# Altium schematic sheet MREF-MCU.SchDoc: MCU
size A4; CompanyName: TRINAMIC; DocumentNumber: 2; SheetNumber: 2; SheetTotal: 5; Author: Indrek Rebane; DrawnBy: Indrek Rebane; Engineer: Indrek Rebane; Organization: Hedgehog OÜ; Address1: Waterloohain 5; Address2: 22769 Hamburg; Address3: Germany; Address4: tmc_info@trinamic.com
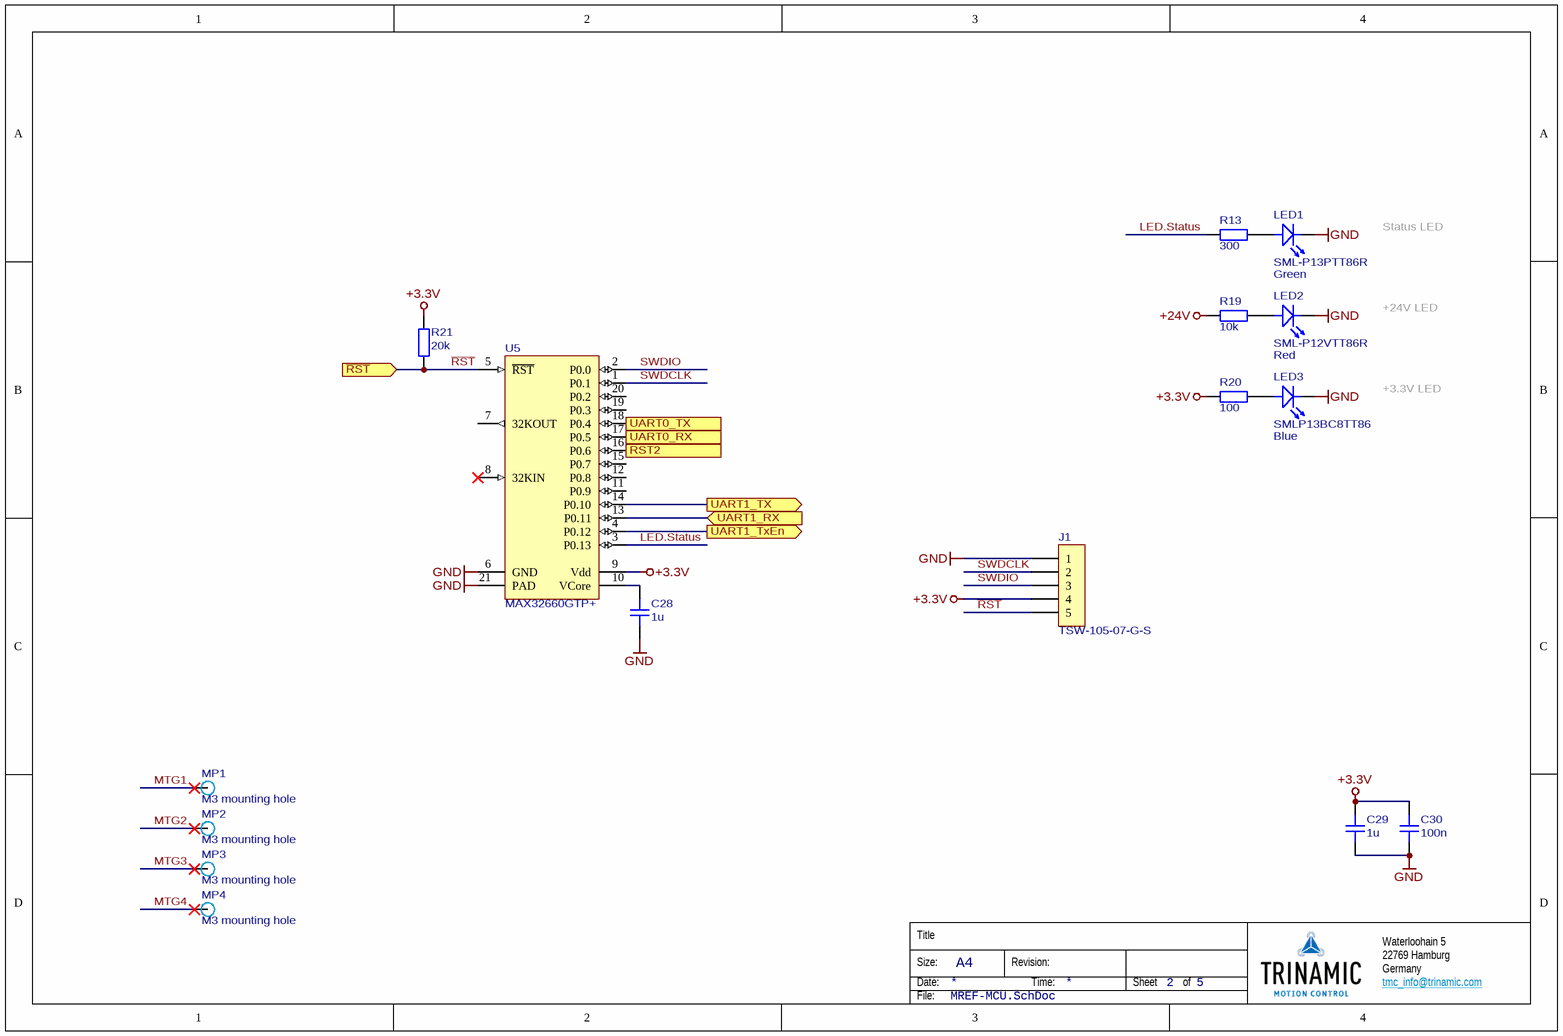
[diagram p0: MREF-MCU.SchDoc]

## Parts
C28  value 1u  [CAPC1608N]  (hidden comment: CAPC)
C29  value 1u  [CAPC1608N]  (hidden comment: CAPC)
C30  value 100n  [CAPC1005N]  (hidden comment: CAPC)
J1  Part Number: TSW-105-07-G-S  [SAMTEC_TSW-105-07-G-S]  (hidden comment: HDR1x5)
LED1  value Green  Part Number: SML-P13PTT86R  [LED1005-GREEN]  (hidden comment: DIO-LED)
LED2  value Red  Part Number: SML-P12VTT86R  [LED1005-RED]  (hidden comment: DIO-LED)
LED3  value Blue  Part Number: SMLP13BC8TT86  [LED1005-BLUE]  (hidden comment: DIO-LED)
MP1  Part Number: M3 mounting hole  [MTG3,2_6,4-VIA]  (hidden comment: MTG)  (no BOM)
MP2  Part Number: M3 mounting hole  [MTG3,2_6,4-VIA]  (hidden comment: MTG)  (no BOM)
MP3  Part Number: M3 mounting hole  [MTG3,2_6,4-VIA]  (hidden comment: MTG)  (no BOM)
MP4  Part Number: M3 mounting hole  [MTG3,2_6,4-VIA]  (hidden comment: MTG)  (no BOM)
R13  value 300  [RESC1005N]  (hidden comment: RESC)
R19  value 10k  [RESC1608N]  (hidden comment: RESC)
R20  value 100  [RESC1005N]  (hidden comment: RESC)
R21  value 20k  [RESC1005N]  (hidden comment: RESC)
U5  MAX32660GTP+  [QFN50P400X400X80_HS-21N]

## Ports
RST2 (out), UART0_RX (in), UART0_TX (out), UART1_RX (in), UART1_TX (out), UART1_TxEn (out), ~{RST} (in)

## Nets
+3.3V: C29.2 C30.2 J1.4 R20.1 R21.1 U5.9(Vdd)
+24V: R19.1
GND: C28.1 C29.1 C30.1 J1.1 LED1.1 LED2.1 LED3.1 U5.6(GND) U5.21(PAD)
~{RST}: J1.5 R21.2 U5.5(~{RST}) ; port ~{RST}
LED.Status: R13.1 U5.3(P0.13)
MTG1: MP1.1(GND)
MTG2: MP2.1(GND)
MTG3: MP3.1(GND)
MTG4: MP4.1(GND)
RST2: U5.16(P0.6) ; port RST2
SWDCLK: J1.2 U5.1(P0.1)
SWDIO: J1.3 U5.2(P0.0)
UART0_RX: U5.17(P0.5) ; port UART0_RX
UART0_TX: U5.18(P0.4) ; port UART0_TX
UART1_RX: U5.13(P0.11) ; port UART1_RX
UART1_TX: U5.14(P0.10) ; port UART1_TX
UART1_TxEn: U5.4(P0.12) ; port UART1_TxEn
NetC28_2: C28.2 U5.10(VCore)
NetLED1_2: LED1.2 R13.2
NetLED2_2: LED2.2 R19.2
NetLED3_2: LED3.2 R20.2

Not connected (* = marked no-connect by the designer): U5 7(32KOUT) 8(32KIN)* 11(P0.9) 12(P0.8) 15(P0.7) 19(P0.3) 20(P0.2)

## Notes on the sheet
- Status LED
- +24V LED
- +3.3V LED

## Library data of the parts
C28 C29 = 20005: Ceramic chip capacitor; Manufacturer: Any; Part Number: 1u, 16V, X5R, 0603 (1608 metric) chip capacitor; Id: 20005; Voltage: 16V
C30 = 20203: Ceramic chip capacitor; Manufacturer: Any; Part Number: 100n, 50V, X7R, 0402 (1005 metric) chip capacitor; Id: 20203; Voltage: 50V
J1 = 50584: 1X5 pin connector; Manufacturer: Samtec; Id: 50584
LED1 = 51636: LED, pin 1 cathode; Manufacturer: ROHM; Id: 51636
LED2 = 51637: LED, pin 1 cathode; Manufacturer: ROHM; Id: 51637
LED3 = 51638: LED, pin 1 cathode; Manufacturer: ROHM; Id: 51638
MP1-MP4 = 50193: Mounting hole; Id: 50193; Value: 3.2x6.4 VIA
R13 = 10332: Chip Resistor; Manufacturer: Any; Part Number: 300, 1%, 62mW, 0402 (1005 metric) chip resistor; Id: 10332; Tolerance: 1%; Power: 62mW
R19 = 10028: Chip Resistor; Manufacturer: Any; Part Number: 10k, 1%, 100mW, 0603 (1608 metric) chip resistor; Id: 10028; Tolerance: 1%; Power: 100mW
R20 = 10009: Chip Resistor; Manufacturer: Any; Part Number: 100, 1%, 62mW, 0402 (1005 metric) chip resistor; Id: 10009; Tolerance: 1%; Power: 62mW
R21 = 10083: Chip Resistor; Manufacturer: Any; Part Number: 20k, 1%, 62mW, 0402 (1005 metric) chip resistor; Id: 10083; Tolerance: 1%; Power: 62mW
U5 = 51470: Manufacturer: Maxim Integrated; Id: 51470; Value: ULP M4F MCU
